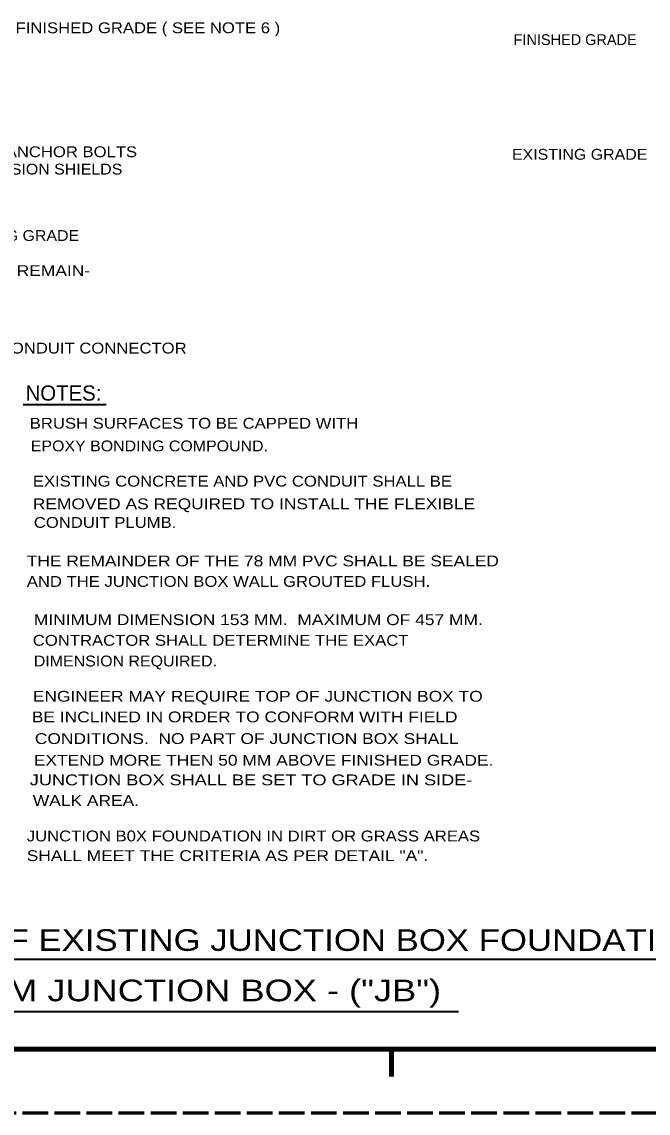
# Model space of a CAD drawing. Extents: x 312583 to 312853, y 144419 to 144586.
# Drawn here: x 312701.4 to 312745.4, y 144418.6 to 144495.2 of the extents above; entities that cross this region are included whole.
import ezdxf
from ezdxf.enums import TextEntityAlignment as Align

# ---------------------------------------------------------------- set-up
doc = ezdxf.new("R2010")
doc.units = 0
doc.header["$LTSCALE"] = 0.3
doc.linetypes.add('LONG_DASHED', pattern=[7.5, 6, -1.5])
doc.layers.add('1', color=7, linetype='Continuous', lineweight=40)
doc.layers.add('2', color=7, linetype='Continuous', lineweight=13)

msp = doc.modelspace()

# ---------------------------------------------------------------- linework, layer by layer
at = {"layer": '1', "lineweight": 158}
for p, q in [((312616.5, 144423.0846), (312849, 144423.0846)), ((312727.35, 144421.1646), (312727.35, 144423.0846))]:
    msp.add_line(p, q, dxfattribs=at)
at = {"layer": '1', "linetype": 'LONG_DASHED', "lineweight": 60}
msp.add_line((312851.75, 144418.5846), (312583.526, 144418.5846), dxfattribs=at)
msp.add_line((312851.75, 144418.5846), (312583.526, 144418.5846), dxfattribs=at)
at = {"layer": '2', "lineweight": 35}
msp.add_line((312701.5055, 144468.3736), (312707.3337, 144468.3736), dxfattribs=at)
at = {"layer": '2', "lineweight": 40}
for p, q in [((312655.2181, 144429.4108), (312758.809, 144429.4108)), ((312677.2561, 144425.7323), (312732.055, 144425.7323))]:
    msp.add_line(p, q, dxfattribs=at)

# ---------------------------------------------------------------- texts
at = {"layer": '2'}
for s, width, p in [('FINISHED GRADE ( SEE NOTE 6 )', 1.15, (312700.9655, 144494.4439)), ('INSTALL-5 ANCHOR BOLTS', 1.15, (312694.1685, 144485.7376)), ('EXISTING GRADE', 1.1, (312735.8048, 144485.5577)), ('AND EXPANSION SHIELDS', 1.1, (312694.1685, 144484.5176)), ('EXISTING GRADE', 1.1, (312695.9239, 144479.852)), ('EXIST. FRAME TO REMAIN-', 1.2, (312690.2049, 144477.3886)), ('53 MM FLEXIBLE CONDUIT CONNECTOR', 1.15, (312690.1129, 144471.9453)), ('BRUSH SURFACES TO BE CAPPED WITH ', 1.15, (312701.9633, 144466.6674)), ('EPOXY BONDING COMPOUND.  ', 1.1, (312702.0343, 144465.0746)), ('EXISTING CONCRETE AND PVC CONDUIT SHALL BE ', 1.15, (312702.176, 144462.5983)), ('REMOVED AS REQUIRED TO INSTALL THE FLEXIBLE  ', 1.2, (312702.176, 144461.0055)), ('CONDUIT PLUMB.  ', 1.15, (312702.2468, 144459.6964)), ('THE REMAINDER OF THE 78 MM PVC SHALL BE SEALED ', 1.2, (312701.7509, 144456.9953)), ('AND THE JUNCTION BOX WALL GROUTED FLUSH. ', 1.15, (312701.7508, 144455.5564)), ('MINIMUM DIMENSION 153 MM.  MAXIMUM OF 457 MM.  ', 1.2, (312702.2469, 144452.8674)), ('CONTRACTOR SHALL DETERMINE THE EXACT   ', 1.15, (312702.176, 144451.4164)), ('DIMENSION REQUIRED. ', 1.1, (312702.2468, 144449.9655)), ('ENGINEER MAY REQUIRE TOP OF JUNCTION BOX TO   ', 1.2, (312702.176, 144447.4892)), ('BE INCLINED IN ORDER TO CONFORM WITH FIELD   ', 1.2, (312702.1051, 144446.0383)), ('CONDITIONS.  NO PART OF JUNCTION BOX SHALL  ', 1.2, (312702.3177, 144444.5164)), ('EXTEND MORE THEN 50 MM ABOVE FINISHED GRADE.   ', 1.2, (312702.2469, 144442.9946)), ('JUNCTION BOX SHALL BE SET TO GRADE IN SIDE-    ', 1.25, (312701.9634, 144441.6146)), ('WALK AREA.  ', 1.2, (312702.176, 144440.1637)), ('JUNCTION B0X FOUNDATION IN DIRT OR GRASS AREAS', 1.15, (312701.7509, 144437.6753)), ('SHALL MEET THE CRITERIA AS PER DETAIL "A".', 1.2, (312701.7509, 144436.2953))]:
    msp.add_text(s, height=0.76, dxfattribs=dict(at, width=width)).set_placement(p)
msp.add_text('FINISHED GRADE', height=0.76, dxfattribs=at).set_placement((312735.9179, 144493.6137))
msp.add_text('NOTES:', height=1.07, dxfattribs=at).set_placement((312704.3267, 144468.6363), align=Align.CENTER)
for s, width, p in [('CAPPING DETAILS FOR EXTENSIONS OF EXISTING JUNCTION BOX FOUNDATION - ("JBF")', 1.2, (312706.6171, 144429.9842)), ('AND 450 BY 900 MM JUNCTION BOX - ("JB")', 1.25, (312704.5168, 144426.4459))]:
    msp.add_text(s, height=1.52, dxfattribs=dict(at, width=width)).set_placement(p, align=Align.CENTER)

doc.saveas('drawing.dxf')
